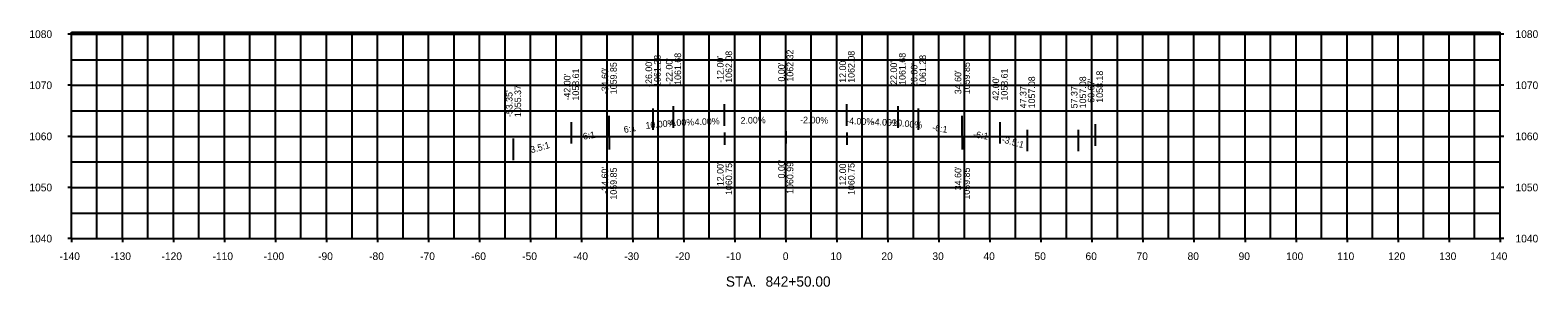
# Model space of a CAD drawing. Extents: x -148 to 147, y 1031 to 1081.
import ezdxf

# ---------------------------------------------------------------- set-up
doc = ezdxf.new("R2010")
doc.units = 0
for name, color, linetype in [('brgConstructionLines', 7, 'Continuous'), ('Default', 7, 'Continuous'), ('Revetment', 7, 'Continuous'), ('TextAlignment', 7, 'Continuous'), ('TextAlignmentLrg', 7, 'Continuous')]:
    doc.layers.add(name, color=color, linetype=linetype)

msp = doc.modelspace()

# ---------------------------------------------------------------- linework, layer by layer
at = {"layer": 'brgConstructionLines'}
for p, q in [((-140, 1080.37), (140, 1080.37)), ((-140, 1040), (-140, 1080.37)), ((140, 1040), (140, 1080.37)), ((-140, 1040), (140, 1040))]:
    msp.add_line(p, q, dxfattribs=at)
at = {"layer": 'Revetment'}
for p, q in [((-34.6, 1059.85), (-34.6, 1064.05)), ((-26, 1061.28), (-26, 1065.48)), ((-22, 1061.68), (-22, 1065.88)), ((-12, 1062.08), (-12, 1066.28)), ((-12, 1062.08), (-12, 1066.28)), ((0, 1062.32), (0, 1066.52)), ((0, 1062.32), (0, 1066.52)), ((0, 1062.32), (0, 1066.52)), ((0, 1062.32), (0, 1066.52)), ((12, 1062.08), (12, 1066.28)), ((12, 1062.08), (12, 1066.28)), ((22, 1061.68), (22, 1065.88)), ((26, 1061.28), (26, 1065.48)), ((34.6, 1059.85), (34.6, 1064.05)), ((34.6, 1059.85), (34.6, 1064.05)), ((-42, 1058.61), (-42, 1062.81)), ((-12, 1060.75), (-12, 1058.35)), ((0, 1060.99), (0, 1058.59)), ((0, 1060.99), (0, 1058.59)), ((0, 1060.99), (0, 1058.59)), ((12, 1060.75), (12, 1058.35)), ((42, 1058.61), (42, 1062.81)), ((47.37, 1057.08), (47.37, 1061.28)), ((57.37, 1057.08), (57.37, 1061.28)), ((60.67, 1058.18), (60.67, 1062.38)), ((-53.35, 1055.37), (-53.35, 1059.57)), ((-34.6, 1059.85), (-34.6, 1057.45)), ((34.6, 1059.85), (34.6, 1057.45))]:
    msp.add_line(p, q, dxfattribs=at)
at = {"layer": 'TextAlignment'}
for p, q in [((-135, 1040), (-135, 1080.37)), ((-125, 1040), (-125, 1080.37)), ((-115, 1040), (-115, 1080.37)), ((-105, 1040), (-105, 1080.37)), ((-95, 1040), (-95, 1080.37)), ((-85, 1040), (-85, 1080.37)), ((-75, 1040), (-75, 1080.37)), ((-65, 1040), (-65, 1080.37)), ((-55, 1040), (-55, 1080.37)), ((-45, 1040), (-45, 1080.37)), ((-35, 1040), (-35, 1080.37)), ((-25, 1040), (-25, 1080.37)), ((-15, 1040), (-15, 1080.37)), ((-5, 1040), (-5, 1080.37)), ((5, 1040), (5, 1080.37)), ((15, 1040), (15, 1080.37)), ((25, 1040), (25, 1080.37)), ((35, 1040), (35, 1080.37)), ((45, 1040), (45, 1080.37)), ((55, 1040), (55, 1080.37)), ((65, 1040), (65, 1080.37)), ((75, 1040), (75, 1080.37)), ((85, 1040), (85, 1080.37)), ((95, 1040), (95, 1080.37)), ((105, 1040), (105, 1080.37)), ((115, 1040), (115, 1080.37)), ((125, 1040), (125, 1080.37)), ((135, 1040), (135, 1080.37)), ((-140, 1075), (140, 1075)), ((-140, 1065), (140, 1065)), ((-140, 1055), (140, 1055)), ((-140, 1045), (140, 1045))]:
    msp.add_line(p, q, dxfattribs=at)
at = {"layer": 'TextAlignmentLrg'}
for p, q in [((-140, 1080), (-140.72, 1080)), ((-140, 1080), (140, 1080)), ((-130, 1040), (-130, 1080.37)), ((-120, 1040), (-120, 1080.37)), ((-110, 1040), (-110, 1080.37)), ((-100, 1040), (-100, 1080.37)), ((-90, 1040), (-90, 1080.37)), ((-80, 1040), (-80, 1080.37)), ((-70, 1040), (-70, 1080.37)), ((-60, 1040), (-60, 1080.37)), ((-50, 1040), (-50, 1080.37)), ((-40, 1040), (-40, 1080.37)), ((-30, 1040), (-30, 1080.37)), ((-20, 1040), (-20, 1080.37)), ((-10, 1040), (-10, 1080.37)), ((0, 1040), (0, 1080.37)), ((10, 1040), (10, 1080.37)), ((20, 1040), (20, 1080.37)), ((30, 1040), (30, 1080.37)), ((40, 1040), (40, 1080.37)), ((50, 1040), (50, 1080.37)), ((60, 1040), (60, 1080.37)), ((70, 1040), (70, 1080.37)), ((80, 1040), (80, 1080.37)), ((90, 1040), (90, 1080.37)), ((100, 1040), (100, 1080.37)), ((110, 1040), (110, 1080.37)), ((120, 1040), (120, 1080.37)), ((130, 1040), (130, 1080.37)), ((140.72, 1080), (140, 1080)), ((-140, 1070), (-140.72, 1070)), ((-140, 1070), (140, 1070)), ((140.72, 1070), (140, 1070)), ((-140, 1060), (-140.72, 1060)), ((-140, 1060), (140, 1060)), ((140.72, 1060), (140, 1060)), ((-140, 1050), (-140.72, 1050)), ((-140, 1050), (140, 1050)), ((140.72, 1050), (140, 1050)), ((-140, 1040), (-140.72, 1040)), ((-140, 1040), (-140, 1039.28)), ((-130, 1040), (-130, 1039.28)), ((-120, 1040), (-120, 1039.28)), ((-110, 1040), (-110, 1039.28)), ((-100, 1040), (-100, 1039.28)), ((-90, 1040), (-90, 1039.28)), ((-80, 1040), (-80, 1039.28)), ((-70, 1040), (-70, 1039.28)), ((-60, 1040), (-60, 1039.28)), ((-50, 1040), (-50, 1039.28)), ((-40, 1040), (-40, 1039.28)), ((-30, 1040), (-30, 1039.28)), ((-20, 1040), (-20, 1039.28)), ((-10, 1040), (-10, 1039.28)), ((0, 1040), (0, 1039.28)), ((10, 1040), (10, 1039.28)), ((20, 1040), (20, 1039.28)), ((30, 1040), (30, 1039.28)), ((40, 1040), (40, 1039.28)), ((50, 1040), (50, 1039.28)), ((60, 1040), (60, 1039.28)), ((70, 1040), (70, 1039.28)), ((80, 1040), (80, 1039.28)), ((90, 1040), (90, 1039.28)), ((100, 1040), (100, 1039.28)), ((110, 1040), (110, 1039.28)), ((120, 1040), (120, 1039.28)), ((130, 1040), (130, 1039.28)), ((140, 1040), (140, 1039.28)), ((140.72, 1040), (140, 1040))]:
    msp.add_line(p, q, dxfattribs=at)

# ---------------------------------------------------------------- texts
at = {"layer": 'Default'}
for s, height, p in [('1080', 1.5, (-148.23, 1079.25)), ('1080', 1.5, (143, 1079.25)), ('1070', 1.5, (-148.23, 1069.25)), ('1070', 1.5, (143, 1069.25)), ('1060', 1.5, (-148.23, 1059.25)), ('1060', 1.5, (143, 1059.25)), ('1050', 1.5, (-148.23, 1049.25)), ('1050', 1.5, (143, 1049.25)), ('1040', 1.5, (-148.23, 1039.25)), ('1040', 1.5, (143, 1039.25)), ('-140', 1.5, (-142.33, 1035.8)), ('-130', 1.5, (-132.33, 1035.8)), ('-120', 1.5, (-122.33, 1035.8)), ('-110', 1.5, (-112.33, 1035.8)), ('-100', 1.5, (-102.33, 1035.8)), ('-90', 1.5, (-91.65, 1035.8)), ('-80', 1.5, (-81.65, 1035.8)), ('-70', 1.5, (-71.65, 1035.8)), ('-60', 1.5, (-61.65, 1035.8)), ('-50', 1.5, (-51.65, 1035.8)), ('-40', 1.5, (-41.65, 1035.8)), ('-30', 1.5, (-31.65, 1035.8)), ('-20', 1.5, (-21.65, 1035.8)), ('-10', 1.5, (-11.65, 1035.8)), ('0', 1.5, (-0.58, 1035.8)), ('10', 1.5, (8.74, 1035.8)), ('20', 1.5, (18.74, 1035.8)), ('30', 1.5, (28.74, 1035.8)), ('40', 1.5, (38.74, 1035.8)), ('50', 1.5, (48.74, 1035.8)), ('60', 1.5, (58.74, 1035.8)), ('70', 1.5, (68.74, 1035.8)), ('80', 1.5, (78.74, 1035.8)), ('90', 1.5, (88.74, 1035.8)), ('100', 1.5, (98.06, 1035.8)), ('110', 1.5, (108.06, 1035.8)), ('120', 1.5, (118.06, 1035.8)), ('130', 1.5, (128.06, 1035.8)), ('140', 1.5, (138.06, 1035.8)), ('STA.', 2.004, (-11.74, 1030.6)), ('842+50.00', 2.004, (-3.96, 1030.6))]:
    msp.add_text(s, height=height, dxfattribs=at).set_placement(p)
at = {"layer": 'Revetment'}
for s, rotation, p in [('1061.28', 90, (-24.51, 1069.68)), ('1061.68', 90, (-20.51, 1070.08)), ("-12.00'", 90, (-12.19, 1070.48)), ("-12.00'", 90, (-12.19, 1070.48)), ('1062.08', 90, (-10.51, 1070.48)), ('1062.08', 90, (-10.51, 1070.48)), ('1062.32', 90, (1.49, 1070.72)), ('1062.32', 90, (1.49, 1070.72)), ('1062.32', 90, (1.49, 1070.72)), ('1062.32', 90, (1.49, 1070.72)), ('1062.08', 90, (13.49, 1070.48)), ('1062.08', 90, (13.49, 1070.48)), ('1061.68', 90, (23.49, 1070.08)), ('1061.28', 90, (27.49, 1069.68)), ('1058.61', 90, (-40.51, 1067.01)), ("-34.60'", 90, (-34.8, 1068.25)), ('1059.85', 90, (-33.11, 1068.25)), ("-26.00'", 90, (-26.19, 1069.68)), ("-22.00'", 90, (-22.19, 1070.08)), ("0.00'", 90, (-0.19, 1070.72)), ("0.00'", 90, (-0.19, 1070.72)), ("0.00'", 90, (-0.19, 1070.72)), ("0.00'", 90, (-0.19, 1070.72)), ("12.00'", 90, (11.81, 1070.48)), ("12.00'", 90, (11.81, 1070.48)), ("22.00'", 90, (21.81, 1070.08)), ("26.00'", 90, (25.81, 1069.68)), ("34.60'", 90, (34.41, 1068.25)), ("34.60'", 90, (34.41, 1068.25)), ('1059.85', 90, (36.09, 1068.25)), ('1059.85', 90, (36.09, 1068.25)), ('1058.61', 90, (43.49, 1067.01)), ('1058.18', 90, (62.16, 1066.58)), ('1055.37', 90, (-51.86, 1063.77)), ("-42.00'", 90, (-42.19, 1067.01)), ("42.00'", 90, (41.81, 1067.01)), ("47.37'", 90, (47.17, 1065.48)), ('1057.08', 90, (48.86, 1065.48)), ("57.37'", 90, (57.17, 1065.48)), ('1057.08', 90, (58.86, 1065.48)), ("60.67'", 90, (60.48, 1066.58)), ("-53.35'", 90, (-53.55, 1063.77)), ('2.00%', 1.1458, (-8.85, 1062.47)), ('-2.00%', 358.8542, (2.81, 1062.59)), ('-4.00%', 357.7094, (11.82, 1062.41)), ('6:1', 9.4642, (-39.64, 1059.33)), ('6:1', 9.4642, (-31.64, 1060.66)), ('10.00%', 5.7106, (-27.42, 1061.46)), ('4.00%', 2.2906, (-22.85, 1061.97)), ('4.00%', 2.2906, (-17.85, 1062.17)), ('-4.00%', 357.7094, (16.82, 1062.21)), ('-10.00%', 354.2894, (20.25, 1062.18)), ('-6:1', 350.5358, (28.64, 1061.16)), ('-6:1', 350.5358, (36.64, 1059.83)), ('3.5:1', 15.9446, (-49.84, 1056.7)), ('-3.5:1', 344.0554, (42.21, 1058.88)), ("-12.00'", 90, (-12.19, 1049.68)), ("0.00'", 90, (-0.19, 1051.77)), ("0.00'", 90, (-0.19, 1051.77)), ("0.00'", 90, (-0.19, 1051.77)), ('1060.99', 90, (1.49, 1048.74)), ('1060.99', 90, (1.49, 1048.74)), ('1060.99', 90, (1.49, 1048.74)), ("12.00'", 90, (11.81, 1050.36)), ("-34.60'", 90, (-34.8, 1048.78)), ('1059.85', 90, (-33.11, 1047.63)), ('1060.75', 90, (-10.51, 1048.53)), ('1060.75', 90, (13.49, 1048.53)), ("34.60'", 90, (34.41, 1049.46)), ('1059.85', 90, (36.09, 1047.63))]:
    msp.add_text(s, height=1.296, rotation=rotation, dxfattribs=at).set_placement(p)

doc.saveas('drawing.dxf')
